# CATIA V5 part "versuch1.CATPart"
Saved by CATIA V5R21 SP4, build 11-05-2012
Part number: Part359
Bounding box of the stored display mesh (mm): x -105.386 to 20, y -89.294 to 322.887, z -27.27 to 98.117
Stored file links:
  C:\Users\jburghuber\Desktop\versuch1.CATPart
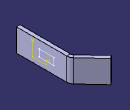
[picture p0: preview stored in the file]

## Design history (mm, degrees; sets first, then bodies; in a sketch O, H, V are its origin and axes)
SheetMetalParameters1: Thickness 20, BendRadius 20, KFactor 0.325257 {= log(min(100,max(20*SheetMetalParameters1.BendRadius,SheetMetalParameters1.Thickness)/SheetMetalParameters1.Thickness))/log(100)/2}, ReliefRadialLength 1, ReliefAxialLength 2, MinimumBendRadius 0
Body1 (main body)
  Sketch1 on yz-plane, origin (0, 0, 0), H (0, 1, 0), V (0, 0, 1)
    line L1 (-89.2944, -27.2696) -> (196.2337, -27.2696)
    line L2 (196.2337, -27.2696) -> (196.2337, 98.1168)
    line L3 (196.2337, 98.1168) -> (-89.2944, 98.1168)
    line L4 (-89.2944, 98.1168) -> (-89.2944, -27.2696)
    horizontal: L1 H, L3 H
    vertical: L2 V, L4 V
  Wall1: Thickness 20, Profile Sketch1
  d_NewWallOnEdge1: NewWallOnEdge_Length 125.3864, NewWallOnEdge_HeightLimitOffset 0, NewWallOnEdge_WidthOffset1 0, NewWallOnEdge_WidthOffset2 0, NewWallOnEdge_Angle 137, NewWallOnEdge_BendRadiusValue 20 {= SheetMetalParameters1.BendRadius}, NewWallOnEdge_BendTable SheetMetalParameters1, NewWallOnEdge_Edge edge [face of Wall1 | face of Wall1], NewWallOnEdge_GapValue 0, KFacteur 0.325257 {= log(min(100,max(20*d_NewWallOnEdge1.Radius,SheetMetalParameters1.Thickness)/SheetMetalParameters1.Thickness))/log(100)/2}
  Sketch2 on face of Wall1, origin (20, 0, 0), H (0, 1, 0), V (0, 0, 1)
    line L1 (35.8363, 16.7938) -> (117.6491, 16.7938)
    line L2 (117.6491, 16.7938) -> (117.6491, 55.5948)
    line L3 (117.6491, 55.5948) -> (35.8363, 55.5948)
    line L4 (35.8363, 55.5948) -> (35.8363, 16.7938)
    horizontal: L1 H, L3 H
    vertical: L2 V, L4 V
